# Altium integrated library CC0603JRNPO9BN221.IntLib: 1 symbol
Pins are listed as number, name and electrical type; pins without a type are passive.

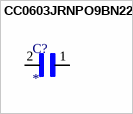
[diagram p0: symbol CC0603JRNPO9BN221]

## CC0603JRNPO9BN221
designator C?
220 pF Â±5% 50V Ceramic Capacitor C0G, NP0 0603 (1608 Metric); MF: Yageo; MP: CC0603JRNPO9BN221
footprint CAPC1608X90
pins: 1, 2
